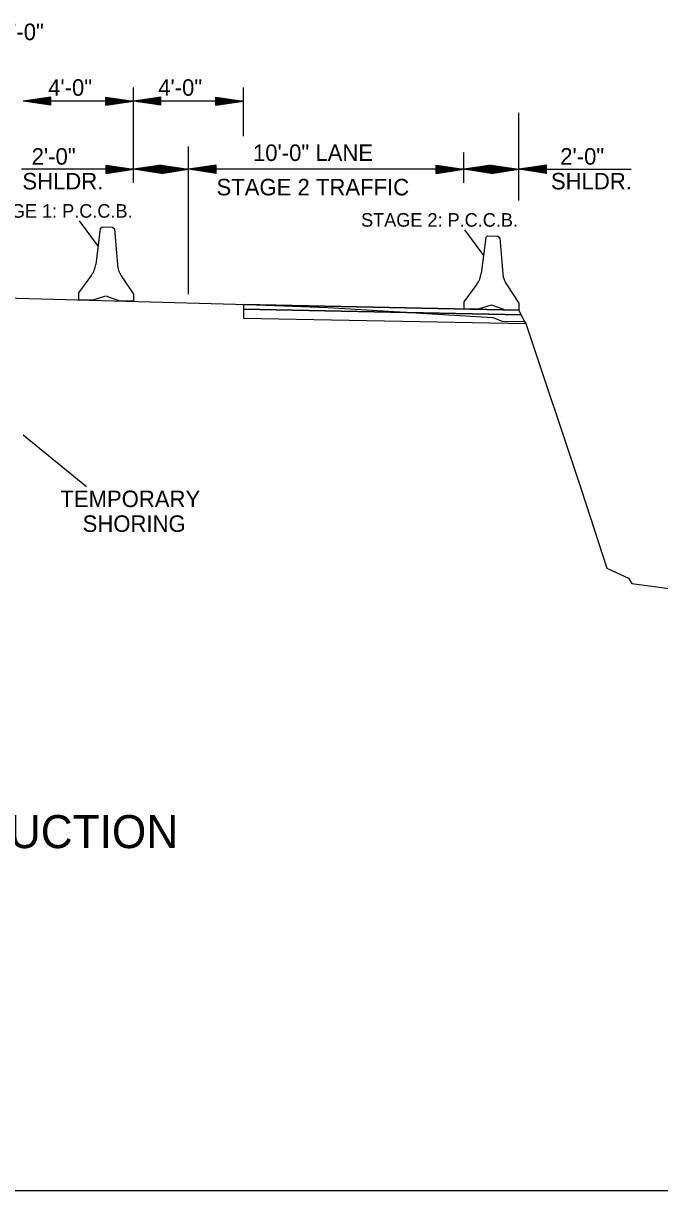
# Model space of a CAD drawing. Extents: x 2829243 to 2838161, y 467639 to 474695.
# Drawn here: x 2830406.5 to 2830637.7, y 469069.4 to 469493.5 of the extents above; entities that cross this region are included whole.
import ezdxf

# ---------------------------------------------------------------- set-up
doc = ezdxf.new("R2010")
doc.units = 0
for name, color, linetype in [('Default', 7, 'Continuous'), ('R_Dimension', 7, 'Continuous'), ('R_Draft', 7, 'Continuous'), ('R_Exist Surface', 7, 'Continuous'), ('R_Fin Surface', 7, 'Continuous'), ('R_MOT', 7, 'Continuous')]:
    doc.layers.add(name, color=color, linetype=linetype)

msp = doc.modelspace()

# ---------------------------------------------------------------- linework, layer by layer
at = {"layer": 'Default'}
msp.add_line((2829486.2, 469069.38), (2831121.84, 469069.38), dxfattribs=at)
at = {"layer": 'R_Dimension'}
for p, q in [((2830446.49, 469446.64), (2830446.49, 469470.2)), ((2830486.49, 469452.56), (2830486.49, 469470.2)), ((2830416.49, 469466.74), (2830406.49, 469465.24)), ((2830446.49, 469465.24), (2830406.49, 469465.24)), ((2830416.49, 469463.74), (2830406.49, 469465.24)), ((2830416.49, 469466.49), (2830408.16, 469465.24)), ((2830416.49, 469463.99), (2830408.16, 469465.24)), ((2830416.49, 469466.23), (2830409.88, 469465.24)), ((2830416.49, 469464.24), (2830409.88, 469465.24)), ((2830416.49, 469465.98), (2830411.55, 469465.24)), ((2830416.49, 469464.49), (2830411.55, 469465.24)), ((2830416.49, 469465.73), (2830413.24, 469465.24)), ((2830416.49, 469464.75), (2830413.24, 469465.24)), ((2830416.49, 469465.47), (2830414.91, 469465.24)), ((2830416.49, 469465), (2830414.91, 469465.24)), ((2830416.49, 469463.74), (2830416.49, 469466.74)), ((2830436.49, 469466.74), (2830446.49, 469465.24)), ((2830436.49, 469463.74), (2830436.49, 469466.74)), ((2830436.49, 469466.49), (2830444.82, 469465.24)), ((2830436.49, 469466.23), (2830443.1, 469465.24)), ((2830436.49, 469465.98), (2830441.44, 469465.24)), ((2830436.49, 469465.73), (2830439.74, 469465.24)), ((2830436.49, 469465.47), (2830438.07, 469465.24)), ((2830436.49, 469463.74), (2830446.49, 469465.24)), ((2830436.49, 469464.75), (2830439.74, 469465.24)), ((2830436.49, 469464.24), (2830443.1, 469465.24)), ((2830436.49, 469463.99), (2830444.82, 469465.24)), ((2830436.49, 469464.49), (2830441.44, 469465.24)), ((2830436.49, 469465), (2830438.07, 469465.24)), ((2830456.49, 469466.74), (2830446.49, 469465.24)), ((2830486.49, 469465.24), (2830446.49, 469465.24)), ((2830456.49, 469463.74), (2830446.49, 469465.24)), ((2830456.49, 469466.49), (2830448.16, 469465.24)), ((2830456.49, 469463.99), (2830448.16, 469465.24)), ((2830456.49, 469466.23), (2830449.88, 469465.24)), ((2830456.49, 469464.24), (2830449.88, 469465.24)), ((2830456.49, 469465.98), (2830451.55, 469465.24)), ((2830456.49, 469464.49), (2830451.55, 469465.24)), ((2830456.49, 469465.73), (2830453.24, 469465.24)), ((2830456.49, 469464.75), (2830453.24, 469465.24)), ((2830456.49, 469465.47), (2830454.91, 469465.24)), ((2830456.49, 469465), (2830454.91, 469465.24)), ((2830456.49, 469463.74), (2830456.49, 469466.74)), ((2830476.49, 469466.74), (2830486.49, 469465.24)), ((2830476.49, 469463.74), (2830476.49, 469466.74)), ((2830476.49, 469466.49), (2830484.82, 469465.24)), ((2830476.49, 469466.23), (2830483.1, 469465.24)), ((2830476.49, 469465.98), (2830481.44, 469465.24)), ((2830476.49, 469465.73), (2830479.74, 469465.24)), ((2830476.49, 469465.47), (2830478.07, 469465.24)), ((2830476.49, 469463.74), (2830486.49, 469465.24)), ((2830476.49, 469464.75), (2830479.74, 469465.24)), ((2830476.49, 469464.24), (2830483.1, 469465.24)), ((2830476.49, 469463.99), (2830484.82, 469465.24)), ((2830476.49, 469464.49), (2830481.44, 469465.24)), ((2830476.49, 469465), (2830478.07, 469465.24)), ((2830586.54, 469429.19), (2830586.54, 469461)), ((2830466.54, 469395.15), (2830466.54, 469448.81)), ((2830446.54, 469435.56), (2830446.54, 469446.64)), ((2830566.54, 469435.56), (2830566.54, 469446.64)), ((2830586.54, 469435.56), (2830586.54, 469446.64)), ((2830466.54, 469440.5), (2830405.78, 469440.5)), ((2830436.54, 469442), (2830446.54, 469440.5)), ((2830436.54, 469439), (2830436.54, 469442)), ((2830436.54, 469441.75), (2830444.87, 469440.5)), ((2830436.54, 469441.49), (2830443.15, 469440.5)), ((2830436.54, 469441.24), (2830441.48, 469440.5)), ((2830436.54, 469440.99), (2830439.79, 469440.5)), ((2830436.54, 469440.73), (2830438.12, 469440.5)), ((2830436.54, 469439), (2830446.54, 469440.5)), ((2830436.54, 469440.01), (2830439.79, 469440.5)), ((2830436.54, 469439.5), (2830443.15, 469440.5)), ((2830436.54, 469439.25), (2830444.87, 469440.5)), ((2830436.54, 469439.75), (2830441.48, 469440.5)), ((2830436.54, 469440.26), (2830438.12, 469440.5)), ((2830456.54, 469442), (2830446.54, 469440.5)), ((2830456.54, 469439), (2830446.54, 469440.5)), ((2830456.54, 469441.75), (2830448.21, 469440.5)), ((2830456.54, 469439.25), (2830448.21, 469440.5)), ((2830456.54, 469441.49), (2830449.93, 469440.5)), ((2830456.54, 469439.5), (2830449.93, 469440.5)), ((2830456.54, 469441.24), (2830451.59, 469440.5)), ((2830456.54, 469439.75), (2830451.59, 469440.5)), ((2830456.54, 469440.99), (2830453.29, 469440.5)), ((2830456.54, 469440.01), (2830453.29, 469440.5)), ((2830456.54, 469440.73), (2830454.96, 469440.5)), ((2830456.54, 469440.26), (2830454.96, 469440.5)), ((2830456.54, 469442), (2830466.54, 469440.5)), ((2830456.54, 469439), (2830456.54, 469442)), ((2830456.54, 469439), (2830456.54, 469442)), ((2830456.54, 469441.75), (2830464.87, 469440.5)), ((2830456.54, 469441.49), (2830463.15, 469440.5)), ((2830456.54, 469441.24), (2830461.48, 469440.5)), ((2830456.54, 469440.99), (2830459.79, 469440.5)), ((2830456.54, 469440.73), (2830458.12, 469440.5)), ((2830456.54, 469439), (2830466.54, 469440.5)), ((2830456.54, 469440.01), (2830459.79, 469440.5)), ((2830456.54, 469439.5), (2830463.15, 469440.5)), ((2830456.54, 469439.25), (2830464.87, 469440.5)), ((2830456.54, 469439.75), (2830461.48, 469440.5)), ((2830456.54, 469440.26), (2830458.12, 469440.5)), ((2830476.54, 469442), (2830466.54, 469440.5)), ((2830566.54, 469440.5), (2830466.54, 469440.5)), ((2830476.54, 469439), (2830466.54, 469440.5)), ((2830476.54, 469441.75), (2830468.21, 469440.5)), ((2830476.54, 469439.25), (2830468.21, 469440.5)), ((2830476.54, 469441.49), (2830469.93, 469440.5)), ((2830476.54, 469439.5), (2830469.93, 469440.5)), ((2830476.54, 469441.24), (2830471.59, 469440.5)), ((2830476.54, 469439.75), (2830471.59, 469440.5)), ((2830476.54, 469440.99), (2830473.29, 469440.5)), ((2830476.54, 469440.01), (2830473.29, 469440.5)), ((2830476.54, 469440.73), (2830474.96, 469440.5)), ((2830476.54, 469440.26), (2830474.96, 469440.5)), ((2830476.54, 469439), (2830476.54, 469442)), ((2830556.54, 469442), (2830566.54, 469440.5)), ((2830556.54, 469439), (2830556.54, 469442)), ((2830556.54, 469441.75), (2830564.87, 469440.5)), ((2830556.54, 469441.49), (2830563.15, 469440.5)), ((2830556.54, 469441.24), (2830561.48, 469440.5)), ((2830556.54, 469440.99), (2830559.79, 469440.5)), ((2830556.54, 469440.73), (2830558.12, 469440.5)), ((2830556.54, 469439), (2830566.54, 469440.5)), ((2830556.54, 469440.01), (2830559.79, 469440.5)), ((2830556.54, 469439.5), (2830563.15, 469440.5)), ((2830556.54, 469439.25), (2830564.87, 469440.5)), ((2830556.54, 469439.75), (2830561.48, 469440.5)), ((2830556.54, 469440.26), (2830558.12, 469440.5)), ((2830576.54, 469442), (2830566.54, 469440.5)), ((2830566.54, 469440.5), (2830627.29, 469440.5)), ((2830576.54, 469439), (2830566.54, 469440.5)), ((2830576.54, 469441.75), (2830568.21, 469440.5)), ((2830576.54, 469439.25), (2830568.21, 469440.5)), ((2830576.54, 469441.49), (2830569.93, 469440.5)), ((2830576.54, 469439.5), (2830569.93, 469440.5)), ((2830576.54, 469441.24), (2830571.59, 469440.5)), ((2830576.54, 469439.75), (2830571.59, 469440.5)), ((2830576.54, 469440.99), (2830573.29, 469440.5)), ((2830576.54, 469440.01), (2830573.29, 469440.5)), ((2830576.54, 469440.73), (2830574.96, 469440.5)), ((2830576.54, 469440.26), (2830574.96, 469440.5)), ((2830576.54, 469439), (2830576.54, 469442)), ((2830576.54, 469442), (2830586.54, 469440.5)), ((2830576.54, 469439), (2830576.54, 469442)), ((2830576.54, 469441.75), (2830584.87, 469440.5)), ((2830576.54, 469441.49), (2830583.15, 469440.5)), ((2830576.54, 469441.24), (2830581.48, 469440.5)), ((2830576.54, 469440.99), (2830579.79, 469440.5)), ((2830576.54, 469440.73), (2830578.12, 469440.5)), ((2830576.54, 469439), (2830586.54, 469440.5)), ((2830576.54, 469440.01), (2830579.79, 469440.5)), ((2830576.54, 469439.5), (2830583.15, 469440.5)), ((2830576.54, 469439.25), (2830584.87, 469440.5)), ((2830576.54, 469439.75), (2830581.48, 469440.5)), ((2830576.54, 469440.26), (2830578.12, 469440.5)), ((2830596.54, 469442), (2830586.54, 469440.5)), ((2830596.54, 469439), (2830586.54, 469440.5)), ((2830596.54, 469441.75), (2830588.21, 469440.5)), ((2830596.54, 469439.25), (2830588.21, 469440.5)), ((2830596.54, 469441.49), (2830589.93, 469440.5)), ((2830596.54, 469439.5), (2830589.93, 469440.5)), ((2830596.54, 469441.24), (2830591.59, 469440.5)), ((2830596.54, 469439.75), (2830591.59, 469440.5)), ((2830596.54, 469440.99), (2830593.29, 469440.5)), ((2830596.54, 469440.01), (2830593.29, 469440.5)), ((2830596.54, 469440.73), (2830594.96, 469440.5)), ((2830596.54, 469440.26), (2830594.96, 469440.5)), ((2830596.54, 469439), (2830596.54, 469442)), ((2830426.75, 469421.77), (2830433.63, 469412.42)), ((2830566.79, 469418.5), (2830573.67, 469409.15)), ((2830586.54, 469389.35), (2830486.49, 469391.35)), ((2830486.49, 469391.35), (2830486.49, 469391.35)), ((2830486.49, 469391.35), (2830486.49, 469391.35)), ((2830486.49, 469391.35), (2830486.49, 469391.35)), ((2830486.49, 469391.35), (2830486.49, 469389.65)), ((2830486.49, 469389.65), (2830486.49, 469389.65)), ((2830486.49, 469389.65), (2830587.4, 469387.63)), ((2830587.4, 469387.63), (2830486.49, 469389.65)), ((2830486.49, 469389.65), (2830486.49, 469389.65)), ((2830486.49, 469389.65), (2830486.49, 469389.65)), ((2830486.49, 469389.65), (2830486.49, 469389.65)), ((2830486.49, 469389.65), (2830486.49, 469386.35)), ((2830586.54, 469389.35), (2830586.54, 469389.35)), ((2830587.4, 469387.63), (2830586.54, 469389.35)), ((2830586.54, 469389.35), (2830586.54, 469389.35)), ((2830486.49, 469386.35), (2830486.49, 469386.35)), ((2830486.49, 469386.35), (2830589.01, 469384.44)), ((2830589.01, 469384.44), (2830587.4, 469387.63)), ((2830587.4, 469387.63), (2830587.4, 469387.63)), ((2830587.4, 469387.63), (2830587.4, 469387.63)), ((2830406.49, 469344.05), (2830429.42, 469325.27))]:
    msp.add_line(p, q, dxfattribs=at)
at = {"layer": 'R_Exist Surface'}
msp.add_lwpolyline([(2829982.69, 469274.29), (2830084.6, 469265.45), (2830091.16, 469260.07), (2830108.46, 469283.54), (2830112.64, 469309.32), (2830118.31, 469372.62), (2830127.4, 469370.46), (2830142, 469374.34), (2830238.91, 469388.67), (2830290.49, 469393.73), (2830312.76, 469393.71), (2830386.29, 469394.15), (2830461.58, 469392.08), (2830487.94, 469391.31), (2830517.3, 469390.3), (2830577.11, 469386.68), (2830580.48, 469385.31), (2830588.89, 469385.2), (2830609.34, 469323.91), (2830618.48, 469295.56), (2830626.4, 469291.95), (2830627.56, 469289.97), (2830768.41, 469271.07)], dxfattribs=at)
at = {"layer": 'R_Fin Surface'}
for p, q in [((2830486.49, 469391.35), (2830586.54, 469389.35)), ((2830586.54, 469389.35), (2830589.01, 469384.44))]:
    msp.add_line(p, q, dxfattribs=at)
at = {"layer": 'R_MOT'}
for p, q in [((2830434.45, 469418.94), (2830432.81, 469405.9)), ((2830434.45, 469418.94), (2830435.15, 469419.54)), ((2830435.15, 469419.54), (2830438.9, 469419.47)), ((2830438.9, 469419.47), (2830439.58, 469418.83)), ((2830439.58, 469418.83), (2830440.69, 469405.74)), ((2830574.49, 469415.67), (2830572.86, 469402.63)), ((2830574.49, 469415.67), (2830575.2, 469416.28)), ((2830575.2, 469416.28), (2830578.95, 469416.2)), ((2830578.95, 469416.2), (2830579.62, 469415.57)), ((2830579.62, 469415.57), (2830580.74, 469402.47)), ((2830431.27, 469402.02), (2830426.54, 469395.55)), ((2830442.07, 469401.8), (2830446.54, 469395.15)), ((2830571.32, 469398.75), (2830566.59, 469392.28)), ((2830582.12, 469398.54), (2830586.59, 469391.88)), ((2830426.54, 469395.55), (2830426.49, 469393.05)), ((2830431.49, 469392.95), (2830426.49, 469393.05)), ((2830431.49, 469392.95), (2830436.52, 469394.51)), ((2830436.52, 469394.51), (2830441.49, 469392.75)), ((2830441.49, 469392.75), (2830446.49, 469392.65)), ((2830446.54, 469395.15), (2830446.49, 469392.65)), ((2830566.59, 469392.28), (2830566.54, 469389.78)), ((2830571.54, 469389.68), (2830566.54, 469389.78)), ((2830571.54, 469389.68), (2830576.57, 469391.24)), ((2830576.57, 469391.24), (2830581.54, 469389.48)), ((2830581.54, 469389.48), (2830586.54, 469389.38)), ((2830586.59, 469391.88), (2830586.54, 469389.38))]:
    msp.add_line(p, q, dxfattribs=at)
for centre, start, end in [((2830424.54, 469406.94), 323.8622, 352.8452), ((2830448.99, 469406.45), 184.8632, 213.8462), ((2830564.59, 469403.67), 323.8622, 352.8452), ((2830589.04, 469403.18), 184.8632, 213.8462)]:
    msp.add_arc(centre, 8.33, start, end, dxfattribs=at)

# ---------------------------------------------------------------- texts
at = {"layer": 'R_Dimension'}
for s, p in [('2\'-0"', (2830397.98, 469487.42)), ('4\'-0"', (2830415.51, 469467.2)), ('4\'-0"', (2830455.51, 469467.2)), ('2\'-0"', (2830409.53, 469442.17)), ('10\'-0" LANE', (2830489.94, 469443.5)), ('2\'-0"', (2830601.58, 469442.17)), ('SHLDR.', (2830406.15, 469433.17)), ('STAGE 2 TRAFFIC', (2830476.69, 469431.01)), ('SHLDR.', (2830598.2, 469433.17)), ('TEMPORARY', (2830419.95, 469317.74)), ('SHORING', (2830428.05, 469308.74))]:
    msp.add_text(s, height=6, dxfattribs=at).set_placement(p)
at = {"layer": 'R_Draft'}
for s, height, p in [('STAGE 1: P.C.C.B.', 4.9184, (2830389.17, 469422.9)), ('STAGE 2: P.C.C.B.', 4.9184, (2830529.21, 469419.63)), ('STAGE 2 CONSTRUCTION', 12, (2830261.26, 469193.84))]:
    msp.add_text(s, height=height, dxfattribs=at).set_placement(p)
at = {"layer": 'R_MOT'}
for p in [(2830426.56, 469393.11), (2830566.61, 469389.84)]:
    msp.add_text('DWB 1-14-10', height=0.04, rotation=88.8542, dxfattribs=at).set_placement(p)

doc.saveas('drawing.dxf')
